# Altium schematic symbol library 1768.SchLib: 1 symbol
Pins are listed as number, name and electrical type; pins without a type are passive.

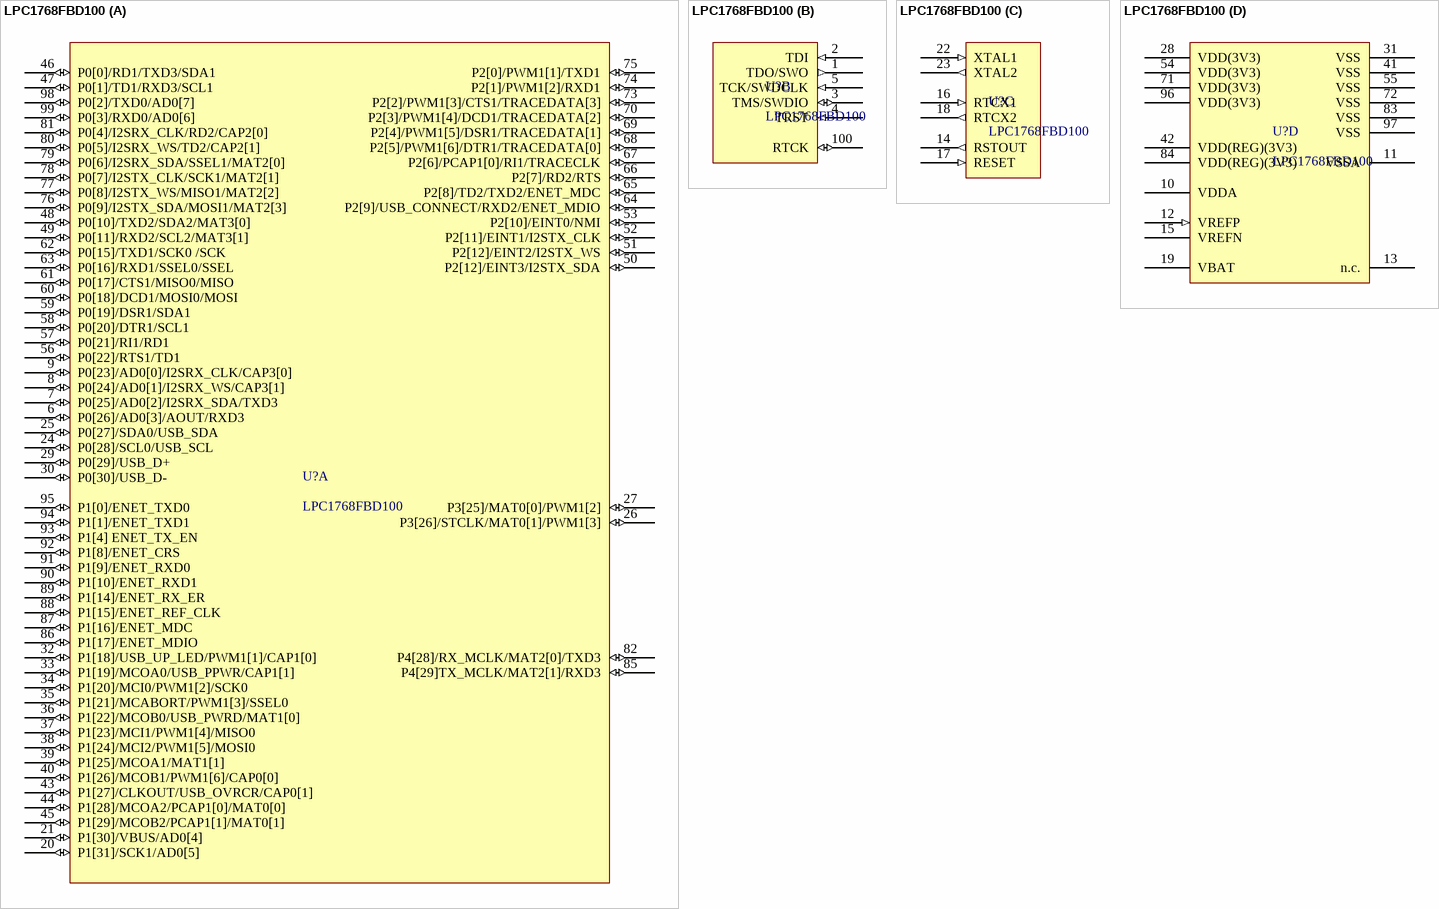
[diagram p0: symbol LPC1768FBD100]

## LPC1768FBD100
designator U?
footprint SOT407-1_N
part A pins: 6 P0[26]/AD0[3]/AOUT/RXD3 (io), 7 P0[25]/AD0[2]/I2SRX_SDA/TXD3 (io), 8 P0[24]/AD0[1]/I2SRX_WS/CAP3[1] (io), 9 P0[23]/AD0[0]/I2SRX_CLK/CAP3[0] (io), 20 P1[31]/SCK1/AD0[5] (io), 21 P1[30]/VBUS/AD0[4] (io), 24 P0[28]/SCL0/USB_SCL (io), 25 P0[27]/SDA0/USB_SDA (io), 26 P3[26]/STCLK/MAT0[1]/PWM1[3] (io), 27 P3[25]/MAT0[0]/PWM1[2] (io), 29 P0[29]/USB_D+ (io), 30 P0[30]/USB_D- (io), 32 P1[18]/USB_UP_LED/PWM1[1]/CAP1[0] (io), 33 P1[19]/MCOA0/USB_PPWR/CAP1[1] (io), 34 P1[20]/MCI0/PWM1[2]/SCK0 (io), 35 P1[21]/MCABORT/PWM1[3]/SSEL0 (io), 36 P1[22]/MCOB0/USB_PWRD/MAT1[0] (io), 37 P1[23]/MCI1/PWM1[4]/MISO0 (io), 38 P1[24]/MCI2/PWM1[5]/MOSI0 (io), 39 P1[25]/MCOA1/MAT1[1] (io), 40 P1[26]/MCOB1/PWM1[6]/CAP0[0] (io), 43 P1[27]/CLKOUT/USB_OVRCR/CAP0[1] (io), 44 P1[28]/MCOA2/PCAP1[0]/MAT0[0] (io), 45 P1[29]/MCOB2/PCAP1[1]/MAT0[1] (io), 46 P0[0]/RD1/TXD3/SDA1 (io), 47 P0[1]/TD1/RXD3/SCL1 (io), 48 P0[10]/TXD2/SDA2/MAT3[0] (io), 49 P0[11]/RXD2/SCL2/MAT3[1] (io), 50 P2[12]/EINT3/I2STX_SDA (io), 51 P2[12]/EINT2/I2STX_WS (io), 52 P2[11]/EINT1/I2STX_CLK (io), 53 P2[10]/EINT0/NMI (io), 56 P0[22]/RTS1/TD1 (io), 57 P0[21]/RI1/RD1 (io), 58 P0[20]/DTR1/SCL1 (io), 59 P0[19]/DSR1/SDA1 (io), 60 P0[18]/DCD1/MOSI0/MOSI (io), 61 P0[17]/CTS1/MISO0/MISO (io), 62 P0[15]/TXD1/SCK0 /SCK (io), 63 P0[16]/RXD1/SSEL0/SSEL (io), 64 P2[9]/USB_CONNECT/RXD2/ENET_MDIO (io), 65 P2[8]/TD2/TXD2/ENET_MDC (io), 66 P2[7]/RD2/RTS (io), 67 P2[6]/PCAP1[0]/RI1/TRACECLK (io), 68 P2[5]/PWM1[6]/DTR1/TRACEDATA[0] (io), 69 P2[4]/PWM1[5]/DSR1/TRACEDATA[1] (io), 70 P2[3]/PWM1[4]/DCD1/TRACEDATA[2] (io), 73 P2[2]/PWM1[3]/CTS1/TRACEDATA[3] (io), 74 P2[1]/PWM1[2]/RXD1 (io), 75 P2[0]/PWM1[1]/TXD1 (io), 76 P0[9]/I2STX_SDA/MOSI1/MAT2[3] (io), 77 P0[8]/I2STX_WS/MISO1/MAT2[2] (io), 78 P0[7]/I2STX_CLK/SCK1/MAT2[1] (io), 79 P0[6]/I2SRX_SDA/SSEL1/MAT2[0] (io), 80 P0[5]/I2SRX_WS/TD2/CAP2[1] (io), 81 P0[4]/I2SRX_CLK/RD2/CAP2[0] (io), 82 P4[28]/RX_MCLK/MAT2[0]/TXD3 (io), 85 P4[29]TX_MCLK/MAT2[1]/RXD3 (io), 86 P1[17]/ENET_MDIO (io), 87 P1[16]/ENET_MDC (io), 88 P1[15]/ENET_REF_CLK (io), 89 P1[14]/ENET_RX_ER (io), 90 P1[10]/ENET_RXD1 (io), 91 P1[9]/ENET_RXD0 (io), 92 P1[8]/ENET_CRS (io), 93 P1[4] ENET_TX_EN (io), 94 P1[1]/ENET_TXD1 (io), 95 P1[0]/ENET_TXD0 (io), 98 P0[2]/TXD0/AD0[7] (io), 99 P0[3]/RXD0/AD0[6] (io)
part B pins: 1 TDO/SWO (out), 2 TDI (in), 3 TMS/SWDIO (io), 4 TRST (in), 5 TCK/SWDCLK (in), 100 RTCK (io)
part C pins: 14 RSTOUT (out), 16 RTCX1 (in), 17 RESET (in), 18 RTCX2 (out), 22 XTAL1 (in), 23 XTAL2 (out)
part D pins: 10 VDDA, 11 VSSA (power), 12 VREFP (in), 13 n.c., 15 VREFN, 19 VBAT, 28 VDD(3V3) (power), 31 VSS (power), 41 VSS (power), 42 VDD(REG)(3V3) (power), 54 VDD(3V3) (power), 55 VSS (power), 71 VDD(3V3) (power), 72 VSS (power), 83 VSS (power), 84 VDD(REG)(3V3) (power), 96 VDD(3V3) (power), 97 VSS (power)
